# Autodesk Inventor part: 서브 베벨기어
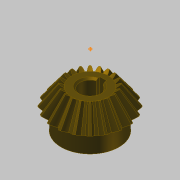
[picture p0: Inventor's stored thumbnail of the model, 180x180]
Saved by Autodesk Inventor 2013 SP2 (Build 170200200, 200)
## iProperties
Created: 2014-10
Part Number: 서브 베벨기어
Material: 강철, 탄소
Document SubType Name: Modeling
Designer: KYOUNG IL JANG
Categories: <?xml version="1.0" encoding="UTF-16"?> <MemberInstance><Categories><FamilyTemplate><FamilyTemplateParameter ValueType="xs:double" Id="1" ObjectReferenceKey="da
Mass: 135.037 g
Surface Area: 63.6518 cm^2
Volume: 17.1585 cm^3
Density: 7.87 g/cm^3
CustomPartVersion: 1
Revision Number: 1
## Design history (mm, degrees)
node "맨 위 점"
node "메쉬 평면2"
sketch "톱니 본체 스케치"
  geometry: L1 (0, 0)-(18.003, -31.331); L2 (18.003, -31.331)-(21.664, -28.891); L3 (21.664, -28.891)-(0, 0); L4 (20, -30)-(0, 0); L5 (10.813, -18.818)-(13.012, -17.352); L6 (18.003, -31.331)-(10.813, -18.818); L7 (21.664, -28.891)-(13.012, -17.352); L8 (0, -39.387)-(0, 6.564) reference; L9 (0, -30)-(21.664, -30)
  constraints: 16 end point, 4 point on line, 3 perpendicular, 2 collinear, 1 horizontal alignment, 1 vertical alignment
  dimensions: "d0" = 40 diameter of L4.start L8 (= da_de); "d1" = 36.00616 diameter of L1.end L8 (= da_dfe); "d2" = 43.3282 diameter of L2.end L8 (= da_dae); "d3" = 14.4 distance between parallel lines of L2 L5 (= da_b); "d4" = 28.8906 vertical distance of L2.end L1.start (= da_ve)
revolve "톱니 본체" sketch "톱니 본체 스케치" stored, may be unused: angle "d5" = 90 deg
node "시작점"
node "톱니 평면"
sketch "시작 스케치"
  geometry: L1 (0, -23.505)-(0, 10.645) reference; L2 (-0.834, -2.928)-(0.834, -2.928); A1 r 8.898 centre (-9.698, -3.713) between (-0.834, -2.928) and (-3.903, 3.04); A2 r 8.898 centre (9.698, -3.713) between (3.903, 3.04) and (0.834, -2.928); A3 r 27.357 centre (0, -24.037) between (3.903, 3.04) and (-3.903, 3.04); 1 further point
  constraints: 6 point on circle, 3 centre point, 3 symmetric about line, 2 end point, 1 coincident, 1 perpendicular, 1 other
  dimensions: "d7" = 8.89846 radius of A1 (= fd_rr); "d8" = 9.69794 horizontal distance of point (0, -24.037) A1.centre (= fd_x); "d9" = 20.32439 vertical distance of point (0, -24.037) A1.centre (= fd_y); "d57" = 27.35701 radius of A3 (= 0.5 x fd_dva + 0.3 x da_he); "d58" = 21.10901 distance from line of A3.centre L2 (= 0.5 x fd_dva - 1.12 x da_he)
node "끝점"
  node "끝 평면"
sketch "3D 스케치 오른쪽"
  node "Helical Curve Right" dims "d65" = 229.90621 (computed from da_dm, da_delta, da_beta), "d66" = 31.5, "d67" = 40 (= da_de), "d68" = -5.88003 (= -da_delta), "d69" = 12.16458 (computed from fd_loft, da_delta)
node "끝 평면 오른쪽"
sketch "끝 스케치 오른쪽"
  geometry: L1 (0, -22.649)-(0, 12.15) reference; L2 (-0.497, -1.72)-(0.497, -1.72); A1 r 5.299 centre (-5.775, -2.187) between (-0.497, -1.72) and (-2.324, 1.834); A2 r 5.299 centre (5.775, -2.187) between (2.324, 1.834) and (0.497, -1.72); A3 r 16.291 centre (0, -14.29) between (2.324, 1.834) and (-2.324, 1.834); 1 further point
  constraints: 6 point on circle, 3 centre point, 3 symmetric about line, 2 end point, 1 coincident, 1 perpendicular, 1 other
  dimensions: "d70" = 5.77526 horizontal distance of A3.centre A1.centre (computed from fd_x, fd_ratio); "d71" = 12.10346 vertical distance of point (0, -14.29) A1.centre (computed from fd_y, fd_ratio); "d72" = 5.29916 radius of A1 (computed from fd_rr, fd_ratio); "d73" = 12.57071 distance from line of point (0, -14.29) L2 (computed from d58, fd_ratio); "d74" = 16.29149 radius of A3 (computed from d57, fd_ratio)
feature "로프트 오른쪽" sketch "끝 스케치 오른쪽" dims "d75" = 0, "d77" = 0, "d79" = 0, "d80" = 90 deg, "d85" = 20, "d92" = 90 deg, "d93" = 90 deg, "da_teethtype" = 0 [user parameter]
sketch "3D 스케치 왼쪽"
  node "Helical Curve Left" dims "d26" = 229.90621 (computed from da_dm, da_delta, da_beta), "d27" = 12.16458 (computed from fd_loft, da_delta), "d28" = 40 (= da_de), "d29" = -5.88003 (= -da_delta)
node "끝 평면 왼쪽"
sketch "끝 스케치 왼쪽" dims "d56" = 10.82768 (derived)
  geometry: L1 (0, -35.087)-(0, 18.089) reference; L2 (-0.497, -1.716)-(0.497, -1.716); A1 r 5.299 centre (-5.775, -2.183) between (-0.497, -1.716) and (-2.324, 1.838); A2 r 5.299 centre (5.775, -2.183) between (2.324, 1.838) and (0.497, -1.716); A3 r 16.291 centre (0, -14.287) between (2.324, 1.838) and (-2.324, 1.838); 2 further points; 1 other entity
  constraints: 6 point on circle, 3 centre point, 3 symmetric about line, 2 end point, 1 coincident, 2 other
  dimensions: "d30" = 5.29916 radius of A1 (computed from fd_rr, fd_ratio); "d31" = 5.77526 horizontal distance of point (0, -14.287) A1.centre (computed from fd_x, fd_ratio); "d32" = 12.10346 vertical distance of A1.centre point (0, -14.287) (computed from fd_y, fd_ratio); "d61" = 16.29149 radius of A3 (computed from d57, fd_ratio); "d62" = 12.57071 distance from line of point (0, -14.287) L2 (computed from d58, fd_ratio)
feature "로프트 왼쪽" sketch "끝 스케치 왼쪽" dims "d35" = 0, "d37" = 0, "d39" = 0, "d40" = 90 deg, "d84" = 10, "d90" = 90 deg, "d91" = 90 deg, "da_teethtype" = 0 [user parameter]
sketch "본체 스케치"
  geometry: L1 (0, -35.038)-(0, -19.531) reference; L2 (18.003, -31.331)-(10.813, -18.818) reference; L3 (10.813, -18.818)-(0, -18.818); L4 (18.003, -31.331)-(0, -31.331)
  constraints: 4 end point, 2 perpendicular, 2 point on line
revolve "본체 고정" sketch "본체 스케치" stored, may be unused: angle "d46" = 90 deg
feature "피치 지름" dims angle "d47" = 90 deg
sketch "스케치8"
  geometry: C1 r 17 at (0, 0); 1 further point
  constraints: 1 centre point, 1 coincident
  dimensions: "d94" = 34 diameter of C1
extrude "돌출1" join sketch "스케치8" distance "d95" = 10; taper "d96" = 0 deg
sketch "스케치9"
  geometry: 1 further point
hole "구멍1" sketch "스케치9" at (0, 0) diameter "d97" = 12; stored, may be unused: countersink angle "d101" = 90 deg, drill point angle "d103" = 118 deg; dims "d98" = 6, "d99" = 4, "d100" = 2, "d102" = 8
sketch "스케치10"
  geometry: 1 further point
sketch "스케치11"
  geometry: 1 further point
sketch "스케치12"
  geometry: L1 (-2, 5.657)-(-2, 7.8); L2 (-2, 7.8)-(2, 7.8); L3 (2, 7.8)-(2, 5.657); A1 r 6 centre (0, 0) between (-2, 5.657) and (2, 5.657) reference; 1 further point
  constraints: 6 end point, 2 parallel, 2 point on circle, 1 perpendicular, 1 vertical
  dimensions: "d104" = 4 distance of L1.end L2.end; "d105" = 13.8 dimension on A1 L2
extrude "돌출2" cut sketch "스케치12" stored distance "d106" = 7; taper "d107" = 0 deg
chamfer "모따기1" distance "d108" = 1; stored, may be unused: second distance "d109" = 2, angle "d110" = 45 deg
body "Solid1"
feature "로프트" dims "d17" = 0, "d18" = 90 deg, "d19" = 0, "d20" = 90 deg, "d89" = 0, "da_teethtype" = 0 [user parameter]
pattern_circular "원형 패턴" dims angle "d22" = 360 deg, "d88" = 0, "da_teethtype" = 0 [user parameter]
pattern_circular "원형 패턴 오른쪽" dims angle "d82" = 360 deg, "da_teethtype" = 0 [user parameter]
pattern_circular "원형 패턴 왼쪽" dims angle "d42" = 360 deg, "da_teethtype" = 0 [user parameter]
sketch "끝 스케치"
  geometry: L1 (0, -15.359)-(0, 6.983) reference; L2 (-0.497, -1.72)-(0.497, -1.72); A1 r 5.299 centre (-5.775, -2.187) between (-0.497, -1.72) and (-2.324, 1.834); A2 r 5.299 centre (5.775, -2.187) between (2.324, 1.834) and (0.497, -1.72); A3 r 16.291 centre (0, -14.29) between (2.324, 1.834) and (-2.324, 1.834); 1 further point
  constraints: 6 point on circle, 3 centre point, 3 symmetric about line, 2 end point, 1 coincident, 1 other
  dimensions: "d12" = 5.29916 radius of A1 (computed from fd_rr, fd_ratio); "d15" = 5.77526 horizontal distance of A1.centre point (0, -14.29) (computed from fd_x, fd_ratio); "d16" = 12.10346 vertical distance of A1.centre point (0, -14.29) (computed from fd_y, fd_ratio); "d59" = 16.29149 radius of A3 (computed from d57, fd_ratio); "d60" = 12.57071 distance from line of A3.centre L2 (computed from d58, fd_ratio)
sketch "Sketch6"
  geometry: L1 (20, -30)-(0, 0) reference; L2 (0, -37.8)-(0, 6.3) reference
body "Srf1"
other parameters: "da_b" = 14.4 [user parameter; used in 2 equation terms], "da_de" = 40 [user parameter; used in 4 equation terms], "da_dae" = 43.3282 [user parameter; used in 2 equation terms], "da_dfe" = 36.00616 [user parameter; used in 1 equation term], "da_le" = 36.05551 [user parameter; used in 1 equation term], "da_omega" = 90 deg [user parameter; used in 1 equation term], "da_beta" = 0 [user parameter; used in 2 equation terms], "da_delta" = 5.88003 [user parameter; used in 8 equation terms], "da_alpha" = 20 deg [user parameter; used in 2 equation terms], "da_he" = 4.4 [user parameter; used in 4 equation terms], "da_ve" = 28.8906 [user parameter; used in 1 equation term], "fd_dv" = 48.07402 (computed from da_de, da_delta) [user parameter; used in 1 equation term], "fd_dva" = 52.07402 (computed from da_dae, da_delta) [user parameter; used in 3 equation terms], "fd_dvb" = 45.1748 (computed from fd_dv, da_alpha) [user parameter; used in 2 equation terms], "da_zv" = 240.37008 [user parameter; used in 1 equation term], "fd_loft" = 14.62 (= da_b + 0.05 x da_he) [user parameter; used in 4 equation terms], "fd_ratio" = 5.95514 (computed from da_le, fd_loft) [user parameter; used in 15 equation terms], "fd_rr" = 8.89846 (computed from fd_dd, fd_dvb) [user parameter; used in 6 equation terms], "fd_angle" = 0.66075 (computed from da_zv) [user parameter; used in 4 equation terms], "fd_x1" = 1.58709 (computed from da_dvw, fd_angle) [user parameter; used in 1 equation term], "fd_y1" = 23.98456 (computed from da_dvw, fd_angle) [user parameter; used in 1 equation term], "fd_x2" = 8.11084 (computed from fd_rr, fd_angle2, fd_angle) [user parameter; used in 1 equation term], "fd_y2" = 3.66016 (computed from fd_rr, fd_angle2, fd_angle) [user parameter; used in 1 equation term], "fd_x" = 9.69794 (= fd_x1 + fd_x2) [user parameter; used in 4 equation terms], "fd_y" = 20.32439 (= fd_y1 - fd_y2) [user parameter; used in 4 equation terms], "fd_angle2" = 3.57832 (computed from fd_dvb, fd_dd, da_alpha) [user parameter; used in 2 equation terms], "fd_dd" = 48.55402 (= fd_dva - 0.8 x da_he) [user parameter; used in 2 equation terms], "da_dvw" = 48.07402 [user parameter; used in 2 equation terms], "d11" = 14.62 (= fd_loft), "da_dm" = 32.01232 [user parameter; used in 2 equation terms], "da_x" = 0 [user parameter], "da_m" = 2 [user parameter], "d48" = 0, "d49" = 0, "d50" = 90 deg (= da_omega), "d51" = 9 deg (computed from da_z), "d52" = 0, "d53" = 0, "d54" = 0
